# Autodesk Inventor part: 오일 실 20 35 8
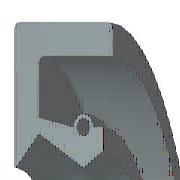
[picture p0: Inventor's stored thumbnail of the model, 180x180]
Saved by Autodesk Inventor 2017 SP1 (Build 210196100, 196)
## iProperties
IsCustomPart: 0
Created: 2018-09
Part Number: 오일 실 20 35 8
Material: 고무
Description: 오일-실
Document SubType Name: Modeling
Standard: KS B 2804
Standards Organization: KS
Language: ko-KR
Size Designation: D - 20 35 8
Categories: <MemberInstance><Categories><Category DisplayName="샤프트 부품" InternalName="7f7aeb1f-a693-4053-b835-cee3144e0d98" Mnemonic="SHFT"><Category DisplayName="실링" Intern
Density: 0.93 g/cm^3
Mass: 2.54606 g
Surface Area: 35.9421 cm^2
Volume: 2.7377 cm^3
Appearance: 고무 - 검은색 - 버전 1.1
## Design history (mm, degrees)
revolve "본체" stored, may be unused: angle "d17" = 90 deg
revolve "스프링1" stored, may be unused: angle "d18" = 90 deg
body "Solid1"
sketch "스케치1"
  geometry: L1 (0, 17.5)-(8, 17.5); L2 (8, 15.75)-(1.75, 15.75); L3 (1.75, 11.75)-(4.9, 10); L4 (4.9, 10)-(0, 10); L5 (0, 0)-(9.586, 0) reference; L6 (4.9, 10)-(6.3, 10.875); L7 (0, 18)-(0, -3) reference; L8 (-1.941, 0)-(11.507, 0) reference; L9 (4.2, 12.1)-(1.75, 12.71); L10 (1.75, 12.71)-(1.75, 15.75); L11 (0, 17.5)-(0, 10.088); L12 (4.9, 10)-(0, 10); L13 (1.75, 11.75)-(0.152, 10.028); L14 (8, 17.5)-(8, 15.75); L15 (5.6, 12.1)-(6.3, 12.1); L16 (6.3, 12.1)-(6.3, 10.875); C1 r 0.455 at (4.9, 12.1); A1 r 0.7 centre (4.9, 12.1) between (5.6, 12.1) and (4.2, 12.1); A2 r 0.088 centre (0.088, 10.088) between (0, 10.088) and (0.152, 10.028); 1 further point
  constraints: 28 end point, 5 horizontal alignment, 5 point on line, 4 point on circle, 4 vertical alignment, 3 centre point, 3 tangent, 2 collinear, 2 horizontal, 2 perpendicular, 1 coincident, 1 parallel
  dimensions: "d0" = 35 diameter of L1 L5 (= SD2); "d1" = 1.75 distance of L1.end L2.start (= SD); "d2" = 0.91 diameter of C1 (= SPDI); "d3" = 1.4 diameter of A1 (= SPDA); "d4" = 20 diameter of L3.end L5 (= NND); "d5" = 23.5 diameter of L3.start L5 (= TKDM); "d7" = 25.42 diameter of L9.end L5 (= TKDM + 0.24 x SWDT); "d8" = 1.75 distance between parallel lines of L11 L10 (= SD); "d9" = 4.9 distance from line of L11 C1.centre (= SPDST); "d10" = 24.2 diameter of C1.centre L5 (= HLDM); "d11" = 0.0875 radius of A2 (= 0.25 x LAB); "d12" = 6.3 distance between parallel lines of L11 L16 (= SDI); "d13" = 21.75 diameter of L6.end L5 (= ABDM); "d14" = 8 distance from line of L11 L1.end (= SWDT)
fillet "모깎기1" dims "d6" = 0.3 (= RR)
other parameters: "SD2" = 35 [user parameter; used in 1 equation term], "SWDT" = 8 [user parameter; used in 2 equation terms], "RR" = 0.3 [user parameter; used in 1 equation term], "SD" = 1.75 [user parameter; used in 2 equation terms], "NND" = 20 [user parameter; used in 1 equation term], "SPDA" = 1.4 [user parameter; used in 1 equation term], "SPDI" = 0.91 [user parameter; used in 1 equation term], "TKDM" = 23.5 [user parameter; used in 2 equation terms], "HLDM" = 24.2 [user parameter; used in 1 equation term], "ABDM" = 21.75 [user parameter; used in 1 equation term], "SDI" = 6.3 [user parameter; used in 1 equation term], "SPDST" = 4.9 [user parameter; used in 1 equation term], "LAB" = 0.35 [user parameter; used in 1 equation term], "d15" = 0, "d16" = 0, "d19" = 0
